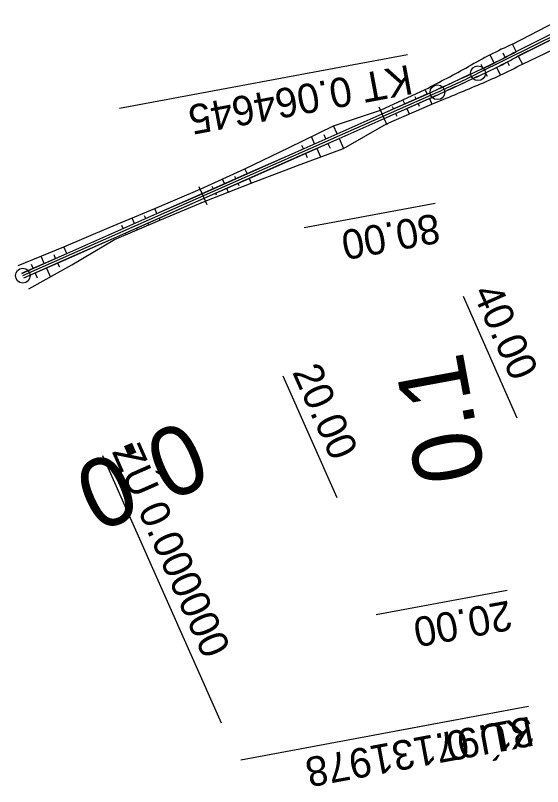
# Model space of a CAD drawing. Extents: x -481685 to -479315, y -1112639 to -1112242.
# Drawn here: x -481684.9 to -481631.4, y -1112639.4 to -1112561.1 of the extents above; entities that cross this region are included whole.
import ezdxf

# ---------------------------------------------------------------- set-up
doc = ezdxf.new("R2010")
doc.units = 0
for name, color, linetype in [('CP14_HATCH_SLOPE_L', 7, 'Continuous'), ('CP14_HATCH_SLOPE_R', 7, 'Continuous'), ('CP14_HECTOMETRY', 7, 'Continuous'), ('CP14_HLBODY', 7, 'Continuous'), ('CP14_HRANA_TELESO', 7, 'Continuous'), ('CP14_KORUNA', 7, 'Continuous'), ('CP14_OSA', 7, 'Continuous'), ('CP14_PRIKOP', 7, 'Continuous'), ('CP14_STANICENI', 7, 'Continuous'), ('CP14_VOZOVKA', 7, 'Continuous'), ('CP14_ZPEVKRAJ', 7, 'Continuous')]:
    doc.layers.add(name, color=color, linetype=linetype)

msp = doc.modelspace()

# ---------------------------------------------------------------- linework, layer by layer
at = {"layer": 'CP14_HATCH_SLOPE_L'}
for p, q in [((-481634.065, -1112564.722), (-481634.434, -1112563.982)), ((-481636.302, -1112565.837), (-481636.657, -1112565.125)), ((-481635.545, -1112564.554), (-481635.545, -1112564.554)), ((-481635.184, -1112565.28), (-481635.364, -1112564.917)), ((-481637.769, -1112565.697), (-481637.769, -1112565.697)), ((-481637.421, -1112566.395), (-481637.595, -1112566.046)), ((-481644.405, -1112569.111), (-481644.405, -1112569.111)), ((-481643.069, -1112569.042), (-481643.27, -1112568.588)), ((-481645.355, -1112570.054), (-481645.541, -1112569.635)), ((-481644.212, -1112569.548), (-481644.309, -1112569.33)), ((-481646.676, -1112570.158), (-481646.676, -1112570.158)), ((-481646.498, -1112570.561), (-481646.587, -1112570.36)), ((-481652.212, -1112573.091), (-481652.577, -1112572.269)), ((-481653.7, -1112572.819), (-481653.7, -1112572.819)), ((-481655.946, -1112573.921), (-481655.946, -1112573.921)), ((-481654.498, -1112574.103), (-481654.823, -1112573.37)), ((-481653.355, -1112573.597), (-481653.527, -1112573.208)), ((-481655.641, -1112574.609), (-481655.794, -1112574.265)), ((-481661.356, -1112577.14), (-481661.566, -1112576.666)), ((-481663.642, -1112578.152), (-481663.843, -1112577.698)), ((-481662.705, -1112577.182), (-481662.705, -1112577.182)), ((-481662.499, -1112577.646), (-481662.602, -1112577.414)), ((-481664.982, -1112578.213), (-481664.982, -1112578.213)), ((-481664.785, -1112578.658), (-481664.884, -1112578.436)), ((-481670.5, -1112581.189), (-481670.723, -1112580.686)), ((-481672.786, -1112582.201), (-481673.028, -1112581.653)), ((-481671.875, -1112581.17), (-481671.875, -1112581.17)), ((-481671.643, -1112581.695), (-481671.759, -1112581.432)), ((-481674.181, -1112582.137), (-481674.181, -1112582.137)), ((-481673.929, -1112582.707), (-481674.055, -1112582.422)), ((-481679.643, -1112585.238), (-481679.941, -1112584.567)), ((-481681.929, -1112586.25), (-481682.254, -1112585.517)), ((-481680.786, -1112585.744), (-481680.942, -1112585.393)), ((-481683.072, -1112586.756), (-481683.242, -1112586.374))]:
    msp.add_line(p, q, dxfattribs=at)
at = {"layer": 'CP14_HATCH_SLOPE_R'}
for p, q in [((-481633.833, -1112565.188), (-481633.423, -1112566.01)), ((-481634.952, -1112565.745), (-481634.753, -1112566.144)), ((-481637.189, -1112566.86), (-481637.003, -1112567.234)), ((-481636.071, -1112566.303), (-481635.686, -1112567.075)), ((-481634.554, -1112566.543), (-481634.554, -1112566.543)), ((-481636.817, -1112567.607), (-481636.817, -1112567.607)), ((-481644.001, -1112570.024), (-481643.879, -1112570.298)), ((-481642.858, -1112569.518), (-481642.611, -1112570.075)), ((-481645.144, -1112570.53), (-481644.906, -1112571.069)), ((-481643.758, -1112570.572), (-481643.758, -1112570.572)), ((-481646.287, -1112571.036), (-481646.17, -1112571.3)), ((-481646.053, -1112571.565), (-481646.053, -1112571.565)), ((-481652.002, -1112573.567), (-481651.557, -1112574.571)), ((-481654.288, -1112574.579), (-481653.905, -1112575.443)), ((-481653.145, -1112574.073), (-481652.938, -1112574.54)), ((-481655.431, -1112575.085), (-481655.255, -1112575.482)), ((-481652.731, -1112575.007), (-481652.731, -1112575.007)), ((-481655.079, -1112575.879), (-481655.079, -1112575.879)), ((-481661.146, -1112577.616), (-481660.93, -1112578.102)), ((-481663.431, -1112578.628), (-481663.262, -1112579.01)), ((-481662.289, -1112578.122), (-481662.192, -1112578.339)), ((-481662.096, -1112578.556), (-481662.096, -1112578.556)), ((-481664.574, -1112579.134), (-481664.501, -1112579.299)), ((-481664.428, -1112579.464), (-481664.428, -1112579.464)), ((-481670.289, -1112581.664), (-481670.195, -1112581.878)), ((-481671.432, -1112582.171), (-481671.388, -1112582.27)), ((-481671.345, -1112582.368), (-481671.345, -1112582.368)), ((-481673.718, -1112583.183), (-481673.681, -1112583.266)), ((-481672.575, -1112582.677), (-481672.495, -1112582.859)), ((-481673.644, -1112583.349), (-481673.644, -1112583.349)), ((-481680.576, -1112586.219), (-481680.398, -1112586.621)), ((-481682.862, -1112587.232), (-481682.639, -1112587.735)), ((-481681.719, -1112586.726), (-481681.312, -1112587.645))]:
    msp.add_line(p, q, dxfattribs=at)
at = {"layer": 'CP14_HECTOMETRY'}
msp.add_circle((-481684.11, -1112587.5), 0.75, dxfattribs=at)
at = {"layer": 'CP14_HLBODY'}
for p, q in [((-481645.092, -1112565.078), (-481674.291, -1112570.507)), ((-481676.012, -1112605.787), (-481663.987, -1112632.944)), ((-481632.783, -1112631.276), (-481661.983, -1112636.705))]:
    msp.add_line(p, q, dxfattribs=at)
for centre in [(-481637.928, -1112566.937), (-481642.036, -1112568.869), (-481684.11, -1112587.5)]:
    msp.add_circle(centre, 0.75, dxfattribs=at)
at = {"layer": 'CP14_HRANA_TELESO'}
for p, q in [((-481634.434, -1112563.982), (-481629.986, -1112561.696)), ((-481633.423, -1112566.01), (-481628.916, -1112563.844)), ((-481647.811, -1112570.681), (-481643.27, -1112568.588)), ((-481652.577, -1112572.269), (-481647.811, -1112570.681)), ((-481647.2, -1112572.062), (-481642.611, -1112570.075)), ((-481657.069, -1112574.472), (-481652.577, -1112572.269)), ((-481651.557, -1112574.571), (-481647.2, -1112572.062)), ((-481661.566, -1112576.666), (-481657.069, -1112574.472)), ((-481656.253, -1112576.316), (-481651.557, -1112574.571)), ((-481666.121, -1112578.729), (-481661.566, -1112576.666)), ((-481660.93, -1112578.102), (-481656.253, -1112576.316)), ((-481665.594, -1112579.918), (-481660.93, -1112578.102)), ((-481670.723, -1112580.686), (-481666.121, -1112578.729)), ((-481670.195, -1112581.878), (-481665.594, -1112579.918)), ((-481675.334, -1112582.621), (-481670.723, -1112580.686)), ((-481674.794, -1112583.839), (-481670.195, -1112581.878)), ((-481679.941, -1112584.567), (-481675.334, -1112582.621))]:
    msp.add_line(p, q, dxfattribs=at)
for centre, radius, start, end in [((-481614.063, -1112609.083), 49.488, 114.30643, 120.09158), ((-481657.164, -1112521.401), 50.533, 292.34231, 298.02191), ((-481779.865, -1112304.942), 296.93, 297.38876, 298.34783), ((-481756.604, -1112289.12), 303.2, 292.084, 293.03695)]:
    msp.add_arc(centre, radius, start, end, dxfattribs=at)
at = {"layer": 'CP14_KORUNA'}
for p, q in [((-481634.065, -1112564.722), (-481629.59, -1112562.492)), ((-481633.833, -1112565.188), (-481629.358, -1112562.958)), ((-481647.641, -1112571.067), (-481643.069, -1112569.042)), ((-481647.43, -1112571.542), (-481642.858, -1112569.518)), ((-481652.212, -1112573.091), (-481647.641, -1112571.067)), ((-481652.002, -1112573.567), (-481647.43, -1112571.542)), ((-481656.784, -1112575.116), (-481652.212, -1112573.091)), ((-481656.574, -1112575.591), (-481652.002, -1112573.567)), ((-481661.356, -1112577.14), (-481656.784, -1112575.116)), ((-481661.146, -1112577.616), (-481656.574, -1112575.591)), ((-481665.928, -1112579.164), (-481661.356, -1112577.14)), ((-481665.717, -1112579.64), (-481661.146, -1112577.616)), ((-481670.5, -1112581.189), (-481665.928, -1112579.164)), ((-481670.289, -1112581.664), (-481665.717, -1112579.64)), ((-481675.072, -1112583.213), (-481670.5, -1112581.189)), ((-481674.861, -1112583.689), (-481670.289, -1112581.664)), ((-481679.643, -1112585.238), (-481675.072, -1112583.213)), ((-481679.433, -1112585.713), (-481674.861, -1112583.689)), ((-481684.215, -1112587.262), (-481679.643, -1112585.238)), ((-481684.005, -1112587.738), (-481679.433, -1112585.713))]:
    msp.add_line(p, q, dxfattribs=at)
for centre, radius, start, end in [((-481658.501, -1112521.249), 49.87, 293.59526, 299.34053), ((-481658.386, -1112521.482), 50.13, 293.60844, 299.32718), ((-481766.279, -1112296.367), 299.22, 294.31617, 295.27153), ((-481766.718, -1112295.424), 300.78, 294.31763, 295.27199)]:
    msp.add_arc(centre, radius, start, end, dxfattribs=at)
at = {"layer": 'CP14_OSA'}
for p, q in [((-481637.928, -1112566.937), (-481626.143, -1112561.066)), ((-481684.11, -1112587.5), (-481642.036, -1112568.869))]:
    msp.add_line(p, q, dxfattribs=at)
msp.add_arc((-481682.525, -1112477.433), 100, 293.88419, 296.48549, dxfattribs=at)
at = {"layer": 'CP14_PRIKOP'}
for p, q in [((-481679.122, -1112586.416), (-481674.794, -1112583.839)), ((-481684.567, -1112586.467), (-481679.941, -1112584.567)), ((-481683.514, -1112588.846), (-481679.122, -1112586.416))]:
    msp.add_line(p, q, dxfattribs=at)
at = {"layer": 'CP14_STANICENI'}
for p, q in [((-481647.13, -1112572.219), (-481647.94, -1112570.39)), ((-481665.418, -1112580.317), (-481666.228, -1112578.488)), ((-481642.285, -1112580.174), (-481655.557, -1112582.642)), ((-481639.438, -1112589.592), (-481633.972, -1112601.936)), ((-481657.725, -1112597.69), (-481652.259, -1112610.033)), ((-481634.973, -1112619.5), (-481648.245, -1112621.968)), ((-481632.784, -1112631.268), (-481646.057, -1112633.736))]:
    msp.add_line(p, q, dxfattribs=at)
at = {"layer": 'CP14_VOZOVKA'}
for p, q in [((-481634.06, -1112564.731), (-481629.585, -1112562.501)), ((-481633.837, -1112565.179), (-481629.362, -1112562.949)), ((-481647.637, -1112571.076), (-481643.065, -1112569.051)), ((-481647.434, -1112571.533), (-481642.862, -1112569.509)), ((-481652.208, -1112573.1), (-481647.637, -1112571.076)), ((-481652.006, -1112573.557), (-481647.434, -1112571.533)), ((-481656.78, -1112575.125), (-481652.208, -1112573.1)), ((-481656.578, -1112575.582), (-481652.006, -1112573.557)), ((-481661.352, -1112577.149), (-481656.78, -1112575.125)), ((-481661.15, -1112577.606), (-481656.578, -1112575.582)), ((-481665.924, -1112579.174), (-481661.352, -1112577.149)), ((-481665.721, -1112579.631), (-481661.15, -1112577.606)), ((-481670.496, -1112581.198), (-481665.924, -1112579.174)), ((-481670.293, -1112581.655), (-481665.721, -1112579.631)), ((-481675.068, -1112583.223), (-481670.496, -1112581.198)), ((-481674.865, -1112583.68), (-481670.293, -1112581.655)), ((-481679.639, -1112585.247), (-481675.068, -1112583.223)), ((-481679.437, -1112585.704), (-481674.865, -1112583.68)), ((-481684.211, -1112587.271), (-481679.639, -1112585.247)), ((-481684.009, -1112587.729), (-481679.437, -1112585.704))]:
    msp.add_line(p, q, dxfattribs=at)
for centre, radius, start, end in [((-481658.499, -1112521.254), 49.875, 293.59552, 299.34027), ((-481658.389, -1112521.478), 50.125, 293.60819, 299.32744), ((-481766.288, -1112296.349), 299.25, 294.31619, 295.27154), ((-481766.709, -1112295.442), 300.75, 294.3176, 295.27198)]:
    msp.add_arc(centre, radius, start, end, dxfattribs=at)
at = {"layer": 'CP14_ZPEVKRAJ'}
for p, q in [((-481634.06, -1112564.731), (-481629.585, -1112562.501)), ((-481633.837, -1112565.179), (-481629.362, -1112562.949)), ((-481647.637, -1112571.076), (-481643.065, -1112569.051)), ((-481647.434, -1112571.533), (-481642.862, -1112569.509)), ((-481652.208, -1112573.1), (-481647.637, -1112571.076)), ((-481652.006, -1112573.557), (-481647.434, -1112571.533)), ((-481656.78, -1112575.125), (-481652.208, -1112573.1)), ((-481656.578, -1112575.582), (-481652.006, -1112573.557)), ((-481661.352, -1112577.149), (-481656.78, -1112575.125)), ((-481661.15, -1112577.606), (-481656.578, -1112575.582)), ((-481665.924, -1112579.174), (-481661.352, -1112577.149)), ((-481665.721, -1112579.631), (-481661.15, -1112577.606)), ((-481670.496, -1112581.198), (-481665.924, -1112579.174)), ((-481670.293, -1112581.655), (-481665.721, -1112579.631)), ((-481675.068, -1112583.223), (-481670.496, -1112581.198)), ((-481674.865, -1112583.68), (-481670.293, -1112581.655)), ((-481679.639, -1112585.247), (-481675.068, -1112583.223)), ((-481679.437, -1112585.704), (-481674.865, -1112583.68)), ((-481684.211, -1112587.271), (-481679.639, -1112585.247)), ((-481684.009, -1112587.729), (-481679.437, -1112585.704))]:
    msp.add_line(p, q, dxfattribs=at)
for centre, radius, start, end in [((-481658.499, -1112521.254), 49.875, 293.59552, 299.34027), ((-481658.389, -1112521.478), 50.125, 293.60819, 299.32744), ((-481766.288, -1112296.349), 299.25, 294.31619, 295.27154), ((-481766.709, -1112295.442), 300.75, 294.3176, 295.27198)]:
    msp.add_arc(centre, radius, start, end, dxfattribs=at)

# ---------------------------------------------------------------- texts
at = {"layer": 'CP14_HECTOMETRY'}
for s, height, rotation, p in [('0.1', 7, 100.48759, (-481637.142, -1112607.866)), ('0.0', 6.999, 203.83855, (-481667.489, -1112602.021))]:
    msp.add_text(s, height=height, rotation=rotation, dxfattribs=at).set_placement(p)
at = {"layer": 'CP14_HLBODY'}
for s, height, rotation, p in [('KT 0.064645', 3, 190.53322, (-481644.908, -1112566.061)), ('ZÚ 0.000000', 2.999, 293.88417, (-481675.098, -1112605.382)), ('KÚ 0.131978', 3, 190.53322, (-481632.599, -1112632.259))]:
    msp.add_text(s, height=height, rotation=rotation, dxfattribs=at).set_placement(p)
at = {"layer": 'CP14_STANICENI'}
for s, height, rotation, p in [('80.00', 3, 190.53322, (-481642.101, -1112581.157)), ('40.00', 2.999, 293.88417, (-481638.524, -1112589.186)), ('20.00', 2.999, 293.88417, (-481656.811, -1112597.284)), ('20.00', 3, 190.53322, (-481634.789, -1112620.483)), ('31.97', 3, 190.53322, (-481632.601, -1112632.251))]:
    msp.add_text(s, height=height, rotation=rotation, dxfattribs=at).set_placement(p)

doc.saveas('drawing.dxf')
